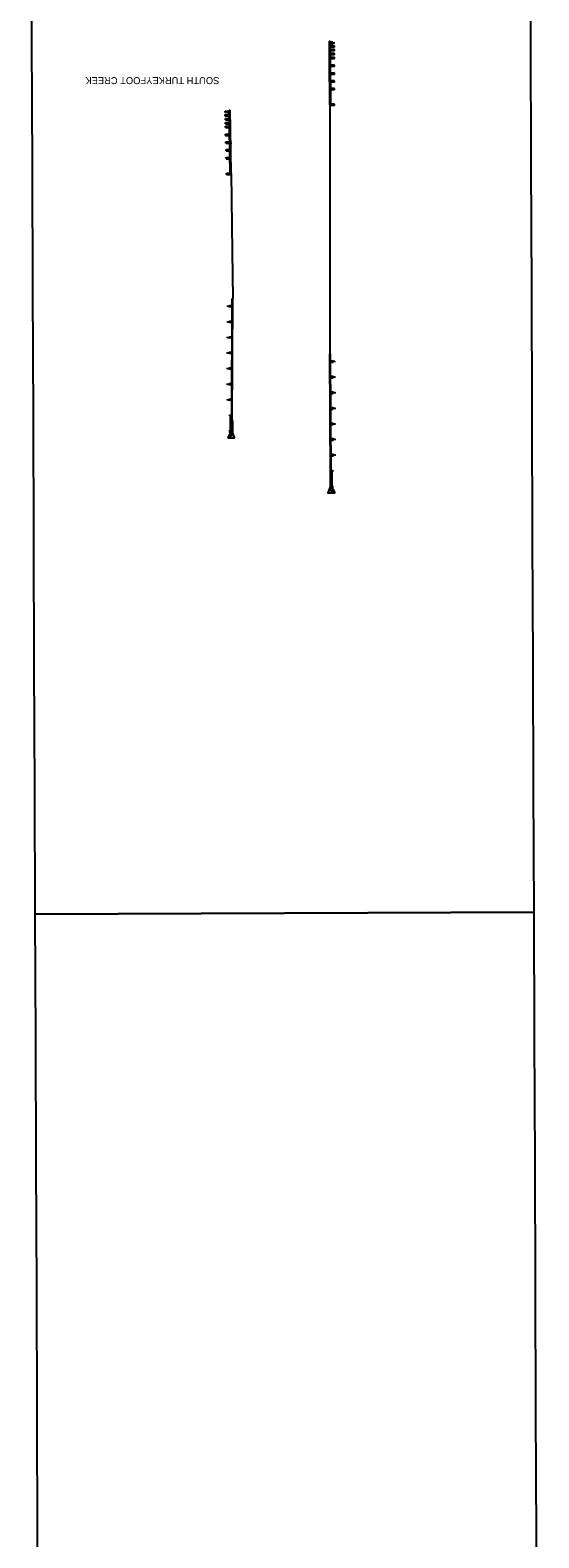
# Model space of a CAD drawing. Extents: x 181105 to 189133, y 406929 to 500404.
# Drawn here: x 181644 to 181848, y 415179 to 415783 of the extents above; entities that cross this region are included whole.
import ezdxf

# ---------------------------------------------------------------- set-up
doc = ezdxf.new("R2010")
doc.units = 0
for name, color, linetype in [('SH_Named_Boundary', 7, 'Continuous'), ('SH_Text', 7, 'Continuous'), ('UT_X_Electric_Cells', 7, 'Continuous'), ('UT_X_Telecom_Cells', 7, 'Continuous')]:
    doc.layers.add(name, color=color, linetype=linetype)

msp = doc.modelspace()

# ---------------------------------------------------------------- linework, layer by layer
at = {"layer": 'SH_Named_Boundary'}
for points in [[(181646.29, 415429.12), (181846.29, 415429.88), (181846.1, 415479.88), (181845.91, 415529.88), (181845.72, 415579.88), (181845.53, 415629.88), (181845.33, 415679.88), (181845.14, 415729.88), (181844.95, 415779.88), (181844.76, 415829.88), (181844.57, 415879.88), (181844.38, 415929.88), (181644.38, 415929.12), (181644.57, 415879.12), (181644.76, 415829.12), (181644.95, 415779.12), (181645.15, 415729.12), (181645.34, 415679.12), (181645.53, 415629.12), (181645.72, 415579.12), (181645.91, 415529.12), (181646.1, 415479.12)], [(181648.2, 414929.12), (181848.2, 414929.89), (181848.01, 414979.89), (181847.82, 415029.89), (181847.63, 415079.89), (181847.44, 415129.89), (181847.25, 415179.89), (181847.05, 415229.88), (181846.86, 415279.88), (181846.67, 415329.88), (181846.48, 415379.88), (181846.29, 415429.88), (181646.29, 415429.12), (181646.48, 415379.12), (181646.67, 415329.12), (181646.86, 415279.12), (181647.06, 415229.12), (181647.25, 415179.12), (181647.44, 415129.12), (181647.63, 415079.12), (181647.82, 415029.12), (181648.01, 414979.12)]]:
    msp.add_lwpolyline(points, close=True, dxfattribs=at)
at = {"layer": 'UT_X_Electric_Cells'}
for p, q in [((181764.31, 415771.74), (181764.26, 415779.07)), ((181764.64, 415779.07), (181764.26, 415779.07)), ((181764.27, 415778.55), (181764.27, 415778.55)), ((181764.34, 415777.98), (181764.33, 415779.06)), ((181764.34, 415777.98), (181764.65, 415777.98)), ((181764.69, 415771.75), (181764.64, 415779.07)), ((181765.61, 415778.66), (181764.65, 415778.65)), ((181764.65, 415778.11), (181765.62, 415778.12)), ((181765.61, 415778.66), (181765.68, 415778.66)), ((181765.62, 415778.12), (181765.67, 415778.12)), ((181765.63, 415778.66), (181765.68, 415778.66)), ((181765.63, 415778.12), (181765.63, 415778.66)), ((181765.67, 415778.12), (181765.67, 415778.32)), ((181765.68, 415778.46), (181765.68, 415778.66)), ((181765.72, 415778.36), (181766.15, 415778.37)), ((181765.73, 415778.41), (181766.13, 415778.42)), ((181766.18, 415778.66), (181766.23, 415778.66)), ((181766.18, 415778.46), (181766.18, 415778.66)), ((181766.2, 415778.12), (181766.2, 415778.32)), ((181766.2, 415778.12), (181766.23, 415778.12)), ((181766.23, 415778.12), (181766.23, 415778.66)), ((181764.44, 415753.55), (181764.31, 415771.74)), ((181766.27, 415777.24), (181764.66, 415777.23)), ((181766.27, 415776.7), (181764.66, 415776.69)), ((181766.27, 415775.68), (181764.67, 415775.67)), ((181766.27, 415775.14), (181764.67, 415775.13)), ((181766.26, 415774.12), (181764.68, 415774.11)), ((181766.26, 415773.58), (181764.68, 415773.57)), ((181766.27, 415772.58), (181764.69, 415772.57)), ((181766.27, 415772.04), (181764.69, 415772.03)), ((181764.83, 415753.02), (181764.69, 415771.75)), ((181765.52, 415773.57), (181765.51, 415774.11)), ((181765.52, 415776.69), (181765.52, 415777.24)), ((181765.53, 415775.13), (181765.52, 415775.67)), ((181765.53, 415772.03), (181765.52, 415772.57)), ((181766.26, 415773.58), (181766.26, 415774.12)), ((181766.27, 415776.7), (181766.27, 415777.24)), ((181766.27, 415775.14), (181766.27, 415775.68)), ((181766.27, 415772.04), (181766.27, 415772.58)), ((181764.35, 415766.6), (181764.36, 415765.51)), ((181764.36, 415765.51), (181764.64, 415765.51)), ((181764.74, 415765.51), (181764.64, 415765.51)), ((181766.32, 415769.44), (181764.71, 415769.43)), ((181766.32, 415768.9), (181764.71, 415768.89)), ((181766.26, 415766.31), (181764.73, 415766.3)), ((181766.26, 415765.77), (181764.74, 415765.76)), ((181765.52, 415765.77), (181765.51, 415766.31)), ((181765.58, 415768.9), (181765.57, 415769.44)), ((181766.26, 415765.77), (181766.26, 415766.31)), ((181766.32, 415768.9), (181766.32, 415769.44)), ((181766.28, 415763.22), (181764.75, 415763.21)), ((181766.28, 415762.68), (181764.76, 415762.67)), ((181766.35, 415760.11), (181764.78, 415760.1)), ((181766.35, 415759.57), (181764.78, 415759.56)), ((181765.53, 415762.68), (181765.53, 415763.22)), ((181765.61, 415759.56), (181765.6, 415760.1)), ((181766.28, 415762.68), (181766.28, 415763.22)), ((181766.35, 415759.57), (181766.35, 415760.11)), ((181766.33, 415753.83), (181764.82, 415753.82)), ((181765.59, 415753.29), (181765.59, 415753.83)), ((181766.33, 415753.29), (181766.33, 415753.83)), ((181722.57, 415749.61), (181724.18, 415749.63)), ((181722.58, 415749.07), (181722.57, 415749.61)), ((181722.58, 415750.48), (181722.58, 415751.02)), ((181722.62, 415751.02), (181722.58, 415751.02)), ((181722.62, 415750.48), (181722.58, 415750.48)), ((181722.58, 415749.07), (181724.19, 415749.09)), ((181722.6, 415748.05), (181724.2, 415748.07)), ((181722.61, 415747.5), (181722.6, 415748.05)), ((181722.61, 415747.5), (181724.21, 415747.53)), ((181722.63, 415750.83), (181722.62, 415751.02)), ((181722.62, 415750.48), (181722.62, 415750.69)), ((181723.09, 415750.74), (181722.67, 415750.73)), ((181723.08, 415750.79), (181722.68, 415750.78)), ((181723.2, 415751.04), (181723.13, 415751.03)), ((181723.13, 415750.83), (181723.13, 415751.03)), ((181723.18, 415751.03), (181723.13, 415751.03)), ((181723.14, 415750.49), (181723.14, 415750.7)), ((181723.2, 415750.5), (181723.14, 415750.49)), ((181723.19, 415750.49), (181723.18, 415751.03)), ((181723.19, 415751.04), (181724.16, 415751.05)), ((181724.17, 415750.51), (181723.2, 415750.49)), ((181723.32, 415749.08), (181723.32, 415749.62)), ((181723.36, 415747.52), (181723.35, 415748.06)), ((181724.26, 415744.15), (181724.15, 415751.47)), ((181724.15, 415751.47), (181724.53, 415751.47)), ((181724.48, 415750.38), (181724.17, 415750.38)), ((181724.48, 415750.38), (181724.46, 415751.47)), ((181724.64, 415744.15), (181724.53, 415751.47)), ((181724.54, 415750.96), (181724.54, 415750.96)), ((181766.33, 415753.29), (181764.83, 415753.28)), ((181722.65, 415746.48), (181724.22, 415746.51)), ((181722.65, 415745.94), (181722.65, 415746.48)), ((181722.65, 415745.94), (181724.23, 415745.97)), ((181722.67, 415744.94), (181724.25, 415744.97)), ((181722.68, 415744.4), (181722.67, 415744.94)), ((181722.68, 415744.4), (181724.25, 415744.43)), ((181722.68, 415741.81), (181724.29, 415741.83)), ((181722.69, 415741.27), (181722.68, 415741.81)), ((181723.4, 415745.96), (181723.39, 415746.5)), ((181723.42, 415744.41), (181723.41, 415744.95)), ((181723.44, 415741.28), (181723.43, 415741.82)), ((181724.53, 415725.42), (181724.26, 415744.15)), ((181724.9, 415725.96), (181724.64, 415744.15)), ((181722.69, 415741.27), (181724.3, 415741.29)), ((181722.81, 415738.68), (181724.34, 415738.7)), ((181722.82, 415738.14), (181722.81, 415738.68)), ((181722.82, 415738.14), (181724.34, 415738.16)), ((181722.86, 415735.59), (181724.38, 415735.61)), ((181722.87, 415735.05), (181722.86, 415735.59)), ((181723.56, 415738.15), (181723.56, 415738.69)), ((181723.61, 415735.06), (181723.61, 415735.6)), ((181724.35, 415737.91), (181724.45, 415737.92)), ((181724.73, 415737.92), (181724.45, 415737.92)), ((181724.71, 415739.01), (181724.73, 415737.92)), ((181722.85, 415732.48), (181724.43, 415732.5)), ((181722.86, 415731.94), (181722.85, 415732.48)), ((181722.86, 415731.94), (181724.43, 415731.96)), ((181722.87, 415735.05), (181724.39, 415735.07)), ((181723.61, 415731.95), (181723.6, 415732.49)), ((181723.01, 415726.2), (181724.52, 415726.22)), ((181723.01, 415725.66), (181723.01, 415726.2)), ((181723.01, 415725.66), (181724.52, 415725.68)), ((181723.76, 415725.67), (181723.75, 415726.21)), ((181725.13, 415627.01), (181725.32, 415675.97)), ((181725.32, 415675.97), (181725.57, 415675.97)), ((181725.38, 415627.01), (181725.57, 415675.97)), ((181723.55, 415672.6), (181723.56, 415673.1)), ((181723.56, 415672.85), (181724.31, 415672.85)), ((181724.3, 415672.6), (181724.31, 415673.1)), ((181724.3, 415672.6), (181725.31, 415673.09)), ((181724.31, 415673.1), (181725.3, 415672.59)), ((181723.53, 415666.35), (181723.53, 415666.85)), ((181723.53, 415666.6), (181724.28, 415666.6)), ((181724.28, 415666.35), (181724.28, 415666.85)), ((181724.28, 415666.85), (181725.28, 415666.34)), ((181724.28, 415666.35), (181725.28, 415666.84)), ((181723.51, 415660.1), (181723.51, 415660.6)), ((181723.51, 415660.35), (181724.26, 415660.35)), ((181724.26, 415660.1), (181724.26, 415660.6)), ((181724.26, 415660.6), (181725.26, 415660.09)), ((181724.26, 415660.1), (181725.26, 415660.59)), ((181723.48, 415653.85), (181723.49, 415654.35)), ((181723.48, 415654.1), (181724.23, 415654.1)), ((181724.23, 415653.85), (181724.24, 415654.35)), ((181724.23, 415653.85), (181725.24, 415654.34)), ((181724.24, 415654.35), (181725.23, 415653.84)), ((181764.68, 415604.77), (181764.49, 415653.73)), ((181764.74, 415653.73), (181764.49, 415653.73)), ((181764.93, 415604.77), (181764.74, 415653.73)), ((181765.75, 415650.86), (181764.75, 415650.35)), ((181765.75, 415650.36), (181764.75, 415650.85)), ((181765.75, 415650.36), (181765.75, 415650.86)), ((181766.5, 415650.36), (181766.5, 415650.86)), ((181723.46, 415647.6), (181723.46, 415648.1)), ((181723.46, 415647.85), (181724.21, 415647.85)), ((181724.21, 415647.6), (181724.21, 415648.1)), ((181724.21, 415648.1), (181725.21, 415647.59)), ((181724.21, 415647.6), (181725.21, 415648.09)), ((181766.5, 415650.61), (181765.75, 415650.61)), ((181723.44, 415641.35), (181723.44, 415641.85)), ((181723.44, 415641.6), (181724.19, 415641.6)), ((181724.19, 415641.35), (181724.19, 415641.85)), ((181724.19, 415641.85), (181725.19, 415641.34)), ((181724.19, 415641.35), (181725.19, 415641.84)), ((181765.78, 415644.11), (181764.77, 415644.6)), ((181765.77, 415644.61), (181764.78, 415644.1)), ((181765.78, 415644.11), (181765.77, 415644.61)), ((181766.52, 415644.36), (181765.77, 415644.36)), ((181766.53, 415644.11), (181766.52, 415644.61)), ((181723.41, 415635.1), (181723.41, 415635.6)), ((181723.41, 415635.35), (181724.16, 415635.35)), ((181724.16, 415635.1), (181724.16, 415635.6)), ((181724.16, 415635.6), (181725.16, 415635.09)), ((181724.16, 415635.1), (181725.16, 415635.59)), ((181725.41, 415635.34), (181725.41, 415635.34)), ((181765.8, 415638.36), (181764.8, 415637.85)), ((181765.8, 415637.86), (181764.8, 415638.35)), ((181765.8, 415637.86), (181765.8, 415638.36)), ((181766.55, 415638.11), (181765.8, 415638.11)), ((181766.55, 415637.86), (181766.55, 415638.36)), ((181724.39, 415628.85), (181724.39, 415629.35)), ((181724.39, 415629.1), (181725.14, 415629.09)), ((181724.39, 415628.85), (181725.14, 415628.84)), ((181724.58, 415628.84), (181724.7, 415628.72)), ((181724.68, 415623.09), (181724.7, 415628.84)), ((181724.8, 415623.09), (181724.83, 415628.84)), ((181724.95, 415628.84), (181724.82, 415628.72)), ((181725.01, 415627.01), (181725.12, 415623.09)), ((181725.01, 415627.01), (181725.51, 415627.01)), ((181725.14, 415628.84), (181725.14, 415629.34)), ((181765.82, 415632.11), (181764.82, 415631.6)), ((181765.82, 415631.61), (181764.82, 415632.1)), ((181765.82, 415631.61), (181765.82, 415632.11)), ((181766.57, 415631.86), (181765.82, 415631.86)), ((181766.57, 415631.61), (181766.57, 415632.11)), ((181724.36, 415622.6), (181724.37, 415623.1)), ((181724.36, 415622.85), (181725.11, 415622.84)), ((181724.37, 415623.1), (181725.12, 415623.09)), ((181724.55, 415623.09), (181724.68, 415623.22)), ((181724.93, 415623.09), (181724.8, 415623.22)), ((181725.11, 415622.59), (181725.12, 415623.09)), ((181765.85, 415625.36), (181764.84, 415625.85)), ((181765.84, 415625.86), (181764.85, 415625.35)), ((181765.85, 415625.36), (181765.84, 415625.86)), ((181766.6, 415625.61), (181765.85, 415625.61)), ((181766.6, 415625.36), (181766.59, 415625.86)), ((181765.87, 415619.61), (181764.87, 415619.1)), ((181765.87, 415619.11), (181764.87, 415619.6)), ((181765.87, 415619.11), (181765.87, 415619.61)), ((181766.62, 415619.36), (181765.87, 415619.36)), ((181766.62, 415619.11), (181766.62, 415619.61)), ((181764.64, 415613.1), (181764.64, 415613.1)), ((181765.89, 415613.36), (181764.89, 415612.85)), ((181765.89, 415612.86), (181764.89, 415613.35)), ((181765.89, 415612.86), (181765.89, 415613.36)), ((181766.64, 415613.11), (181765.89, 415613.11)), ((181766.64, 415612.86), (181766.64, 415613.36)), ((181765.05, 415604.77), (181764.55, 415604.77)), ((181764.92, 415606.6), (181764.92, 415607.1)), ((181765.67, 415606.86), (181764.92, 415606.85)), ((181765.67, 415606.61), (181764.92, 415606.6)), ((181765.05, 415604.77), (181764.94, 415600.85)), ((181765.11, 415606.6), (181765.23, 415606.48)), ((181765.25, 415600.85), (181765.23, 415606.6)), ((181765.48, 415606.61), (181765.36, 415606.48)), ((181765.38, 415600.85), (181765.36, 415606.6)), ((181765.67, 415606.61), (181765.67, 415607.11)), ((181765.69, 415600.86), (181764.94, 415600.85)), ((181764.94, 415600.35), (181764.94, 415600.85)), ((181765.69, 415600.61), (181764.94, 415600.6)), ((181765.13, 415600.85), (181765.25, 415600.98)), ((181765.5, 415600.86), (181765.38, 415600.98)), ((181765.69, 415600.36), (181765.69, 415600.86))]:
    msp.add_line(p, q, dxfattribs=at)
for points in [[(181724.3, 415672.6), (181724.31, 415673.1), (181725.31, 415673.09), (181725.3, 415672.59)], [(181724.28, 415666.35), (181724.28, 415666.85), (181725.28, 415666.84), (181725.28, 415666.34)], [(181724.26, 415660.1), (181724.26, 415660.6), (181725.26, 415660.59), (181725.26, 415660.09)], [(181724.23, 415653.85), (181724.24, 415654.35), (181725.24, 415654.34), (181725.23, 415653.84)], [(181765.75, 415650.36), (181765.75, 415650.86), (181764.75, 415650.85), (181764.75, 415650.35)], [(181724.21, 415647.6), (181724.21, 415648.1), (181725.21, 415648.09), (181725.21, 415647.59)], [(181724.19, 415641.35), (181724.19, 415641.85), (181725.19, 415641.84), (181725.19, 415641.34)], [(181765.78, 415644.11), (181765.77, 415644.61), (181764.77, 415644.6), (181764.78, 415644.1)], [(181724.16, 415635.1), (181724.16, 415635.6), (181725.16, 415635.59), (181725.16, 415635.09)], [(181765.8, 415637.86), (181765.8, 415638.36), (181764.8, 415638.35), (181764.8, 415637.85)], [(181765.82, 415631.61), (181765.82, 415632.11), (181764.82, 415632.1), (181764.82, 415631.6)], [(181726.23, 415620.21), (181725.49, 415622.34), (181724.74, 415622.34), (181723.73, 415620.47), (181723.73, 415620.1), (181726.23, 415620.09)], [(181725.11, 415622.34), (181725.11, 415622.18), (181724.36, 415622.18), (181724.36, 415622.35)], [(181765.85, 415625.36), (181765.84, 415625.86), (181764.84, 415625.85), (181764.85, 415625.35)], [(181765.87, 415619.11), (181765.87, 415619.61), (181764.87, 415619.6), (181764.87, 415619.1)], [(181765.89, 415612.86), (181765.89, 415613.36), (181764.89, 415613.35), (181764.89, 415612.85)], [(181763.83, 415597.97), (181764.57, 415600.1), (181765.32, 415600.1), (181766.32, 415598.23), (181766.33, 415597.86), (181763.83, 415597.85)], [(181764.94, 415600.1), (181764.94, 415599.94), (181765.69, 415599.94), (181765.69, 415600.11)]]:
    msp.add_lwpolyline(points, close=True, dxfattribs=at)
for points in [[(181725.51, 415627.01), (181725.49, 415622.34), (181725.11, 415622.34), (181725.12, 415623.09)], [(181723.73, 415620.1), (181723.73, 415620.22), (181726.23, 415620.21)], [(181764.55, 415604.77), (181764.57, 415600.1), (181764.94, 415600.1), (181764.94, 415600.85)], [(181766.33, 415597.86), (181766.33, 415597.98), (181763.83, 415597.97)]]:
    msp.add_lwpolyline(points, dxfattribs=at)
for centre, start, end in [((181723.61, 415622.35), 273.76144, 359.78251), ((181766.45, 415600.11), 180.21749, 266.23856)]:
    msp.add_arc(centre, 1.88, start, end, dxfattribs=at)
for centre, major_axis, start_param, end_param in [((181765.72, 415778.32), (0.0497, 0.0003), 1.570796, 3.141593), ((181765.73, 415778.46), (-0.0497, -0.0003), 0, 1.570796), ((181766.13, 415778.46), (0.0497, 0.0003), 4.712389, 6.283185), ((181766.15, 415778.32), (0.0497, 0.0003), 0, 1.570796), ((181722.67, 415750.69), (-0.0497, -0.0007), 4.712389, 6.283185), ((181722.68, 415750.83), (-0.0497, -0.0007), 0, 1.570796), ((181723.08, 415750.83), (0.0497, 0.0007), 4.712389, 6.283185), ((181723.09, 415750.7), (-0.0497, -0.0007), 3.141593, 4.712389)]:
    msp.add_ellipse(centre, major_axis=major_axis, ratio=0.906762, start_param=start_param, end_param=end_param, dxfattribs=at)
at = {"layer": 'UT_X_Telecom_Cells'}
msp.add_line((181764.44, 415753.55), (181764.49, 415653.73), dxfattribs=at)
msp.add_lwpolyline([(181724.9, 415725.96), (181725.35, 415694.75), (181725.57, 415675.97)], dxfattribs=at)

# ---------------------------------------------------------------- texts
at = {"layer": 'SH_Text'}
msp.add_text('SOUTH TURKEYFOOT CREEK', height=2.8, rotation=180, dxfattribs=at).set_placement((181720.19, 415764.65))

doc.saveas('drawing.dxf')
